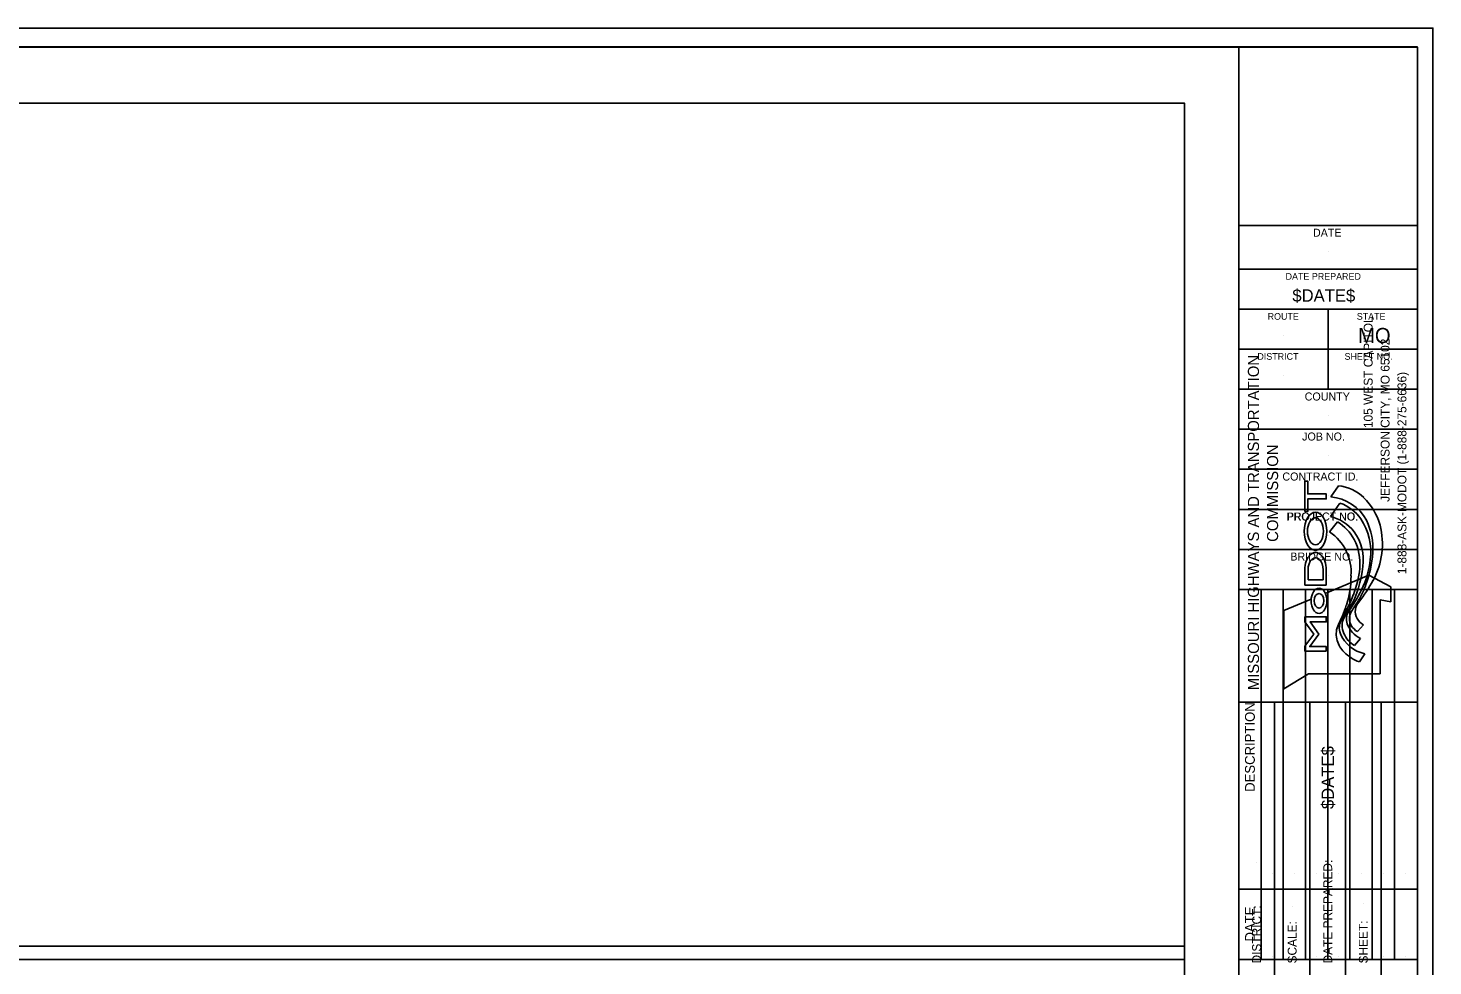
# Model space of a CAD drawing. Extents: x 0 to 31.6, y 0 to 20.8.
# Drawn here: x 15.8 to 31.6, y 10.25 to 20.8 of the extents above; entities that cross this region are included whole.
import ezdxf

# ---------------------------------------------------------------- set-up
doc = ezdxf.new("R2010")
doc.units = 0
for name, color, linetype in [('Border-Border', 7, 'Continuous'), ('Border-Full plan shape', 7, 'Continuous'), ('Border-Full profile shape', 7, 'Continuous'), ('Border-Plan bottom shape', 7, 'Continuous'), ('Border-Plan top shape', 7, 'Continuous'), ('Border-Plotting block', 7, 'Continuous'), ('Border-Title block - Final Plans Consultant Manual Seal', 7, 'Continuous'), ('Border-Title block - Final Plans Electronic Seal', 7, 'Continuous'), ('Border-Title block - Location Survey Electronic Seal', 7, 'Continuous'), ('Border-Xsection shape', 7, 'Continuous')]:
    doc.layers.add(name, color=color, linetype=linetype)

msp = doc.modelspace()

# ---------------------------------------------------------------- linework, layer by layer
at = {"layer": 'Border-Border'}
for p, q in [((0.175, 20.587), (31.425, 20.587)), ((31.425, 20.587), (31.425, 0.212))]:
    msp.add_line(p, q, dxfattribs=at)
at = {"layer": 'Border-Full plan shape'}
msp.add_lwpolyline([(0.806, 19.956), (28.806, 19.956), (28.806, 0.844), (0.806, 0.844)], close=True, dxfattribs=at)
at = {"layer": 'Border-Full profile shape'}
msp.add_lwpolyline([(0.806, 19.956), (28.806, 19.956), (28.806, 0.844), (0.806, 0.844)], close=True, dxfattribs=at)
at = {"layer": 'Border-Plan bottom shape'}
msp.add_lwpolyline([(0.806, 10.325), (28.806, 10.325), (28.806, 0.844), (0.806, 0.844)], close=True, dxfattribs=at)
at = {"layer": 'Border-Plan top shape'}
msp.add_lwpolyline([(0.806, 19.956), (28.806, 19.956), (28.806, 10.475), (0.806, 10.475)], close=True, dxfattribs=at)
at = {"layer": 'Border-Plotting block'}
msp.add_lwpolyline([(0, 0), (31.6, 0), (31.6, 20.8), (0, 20.8)], close=True, dxfattribs=at)
at = {"layer": 'Border-Title block - Final Plans Consultant Manual Seal'}
for p, q in [((29.417, 20.588), (31.425, 20.588)), ((29.417, 20.587), (29.417, 0.212)), ((29.417, 18.58), (31.425, 18.58)), ((30.421, 18.285), (30.421, 18.285)), ((29.417, 18.088), (31.425, 18.088)), ((30.421, 17.793), (30.421, 17.793)), ((29.417, 17.638), (31.425, 17.638)), ((30.421, 16.738), (30.421, 17.638)), ((29.919, 17.343), (29.919, 17.343)), ((30.923, 17.343), (30.923, 17.343)), ((29.417, 17.188), (31.425, 17.188)), ((29.919, 16.895), (29.919, 16.895)), ((30.923, 16.895), (30.923, 16.895)), ((29.417, 16.738), (31.425, 16.738)), ((30.421, 16.443), (30.421, 16.443)), ((29.417, 16.288), (31.425, 16.288)), ((30.421, 15.993), (30.421, 15.993)), ((29.417, 15.838), (31.425, 15.838)), ((30.421, 15.543), (30.421, 15.543)), ((29.417, 15.388), (31.425, 15.388)), ((30.421, 15.093), (30.421, 15.093)), ((29.417, 14.938), (31.425, 14.938)), ((30.421, 14.643), (30.421, 14.643)), ((29.417, 14.488), (31.425, 14.488)), ((29.667, 14.488), (29.667, 10.327)), ((29.917, 14.488), (29.917, 10.327)), ((30.167, 14.488), (30.167, 10.327)), ((30.417, 14.488), (30.417, 10.327)), ((30.667, 14.488), (30.667, 10.327)), ((30.917, 14.488), (30.917, 10.327)), ((31.167, 14.488), (31.167, 10.327)), ((29.417, 11.117), (31.425, 11.117)), ((29.417, 10.327), (31.425, 10.327))]:
    msp.add_line(p, q, dxfattribs=at)
at = {"layer": 'Border-Title block - Final Plans Electronic Seal'}
for p, q in [((29.417, 20.587), (29.417, 0.212)), ((29.417, 18.088), (31.425, 18.088)), ((30.421, 17.793), (30.421, 17.793)), ((29.417, 17.638), (31.425, 17.638)), ((30.421, 16.738), (30.421, 17.638)), ((29.919, 17.343), (29.919, 17.343)), ((30.923, 17.343), (30.923, 17.343)), ((29.417, 17.188), (31.425, 17.188)), ((29.919, 16.895), (29.919, 16.895)), ((30.923, 16.895), (30.923, 16.895)), ((29.417, 16.738), (31.425, 16.738)), ((30.421, 16.443), (30.421, 16.443)), ((29.417, 16.288), (31.425, 16.288)), ((30.421, 15.993), (30.421, 15.993)), ((29.417, 15.838), (31.425, 15.838)), ((30.421, 15.543), (30.421, 15.543)), ((29.417, 15.388), (31.425, 15.388)), ((30.421, 15.093), (30.421, 15.093)), ((29.417, 14.938), (31.425, 14.938)), ((30.421, 14.643), (30.421, 14.643)), ((29.417, 14.488), (31.425, 14.488)), ((29.667, 14.488), (29.667, 10.327)), ((29.917, 14.488), (29.917, 10.327)), ((30.167, 14.488), (30.167, 10.327)), ((30.417, 14.488), (30.417, 10.327)), ((30.667, 14.488), (30.667, 10.327)), ((30.917, 14.488), (30.917, 10.327)), ((31.167, 14.488), (31.167, 10.327)), ((29.792, 11.297), (29.792, 11.297)), ((29.792, 11.297), (29.792, 11.297)), ((30.042, 11.297), (30.042, 11.297)), ((30.042, 11.297), (30.042, 11.297)), ((30.292, 11.297), (30.292, 11.297)), ((30.292, 11.297), (30.292, 11.297)), ((30.542, 11.297), (30.542, 11.297)), ((30.542, 11.297), (30.542, 11.297)), ((30.792, 11.297), (30.792, 11.297)), ((30.792, 11.297), (30.792, 11.297)), ((31.042, 11.297), (31.042, 11.297)), ((31.042, 11.297), (31.042, 11.297)), ((31.296, 11.297), (31.296, 11.297)), ((31.296, 11.297), (31.296, 11.297)), ((29.417, 11.117), (31.425, 11.117)), ((29.417, 10.327), (31.425, 10.327)), ((29.792, 10.362), (29.792, 10.362)), ((29.792, 10.362), (29.792, 10.362)), ((30.042, 10.362), (30.042, 10.362)), ((30.042, 10.362), (30.042, 10.362)), ((30.292, 10.362), (30.292, 10.362)), ((30.292, 10.362), (30.292, 10.362)), ((30.542, 10.362), (30.542, 10.362)), ((30.542, 10.362), (30.542, 10.362)), ((30.792, 10.362), (30.792, 10.362)), ((30.792, 10.362), (30.792, 10.362)), ((31.042, 10.362), (31.042, 10.362)), ((31.042, 10.362), (31.042, 10.362)), ((31.296, 10.362), (31.296, 10.362)), ((31.296, 10.362), (31.296, 10.362))]:
    msp.add_line(p, q, dxfattribs=at)
msp.add_lwpolyline([(29.417, 20.587), (31.425, 20.587), (31.425, 18.088), (29.417, 18.088)], close=True, dxfattribs=at)
at = {"layer": 'Border-Title block - Location Survey Electronic Seal'}
for p, q in [((29.417, 20.587), (29.417, 0.212)), ((29.417, 18.088), (31.425, 18.088)), ((30.537, 15.653), (30.452, 15.528)), ((30.554, 15.458), (30.448, 15.307)), ((30.527, 15.246), (30.438, 15.135)), ((30.16, 14.707), (30.16, 14.534)), ((30.196, 14.594), (30.196, 14.707)), ((30.366, 14.707), (30.366, 14.594)), ((30.401, 14.534), (30.401, 14.707)), ((30.366, 14.594), (30.196, 14.594)), ((30.88, 14.647), (30.39, 14.443)), ((31.127, 14.517), (30.88, 14.647)), ((30.16, 14.534), (30.401, 14.534)), ((31.127, 14.346), (31.127, 14.517)), ((30.231, 14.377), (29.922, 14.249)), ((29.922, 14.249), (29.922, 13.37)), ((31.007, 13.54), (31.007, 14.371)), ((31.007, 14.371), (31.127, 14.346)), ((30.752, 14.013), (30.821, 14.089)), ((30.719, 13.855), (30.786, 13.935)), ((30.773, 13.672), (30.833, 13.764)), ((29.922, 13.37), (30.2, 13.54)), ((30.2, 13.54), (31.007, 13.54)), ((29.417, 13.22), (31.425, 13.22)), ((29.817, 13.22), (29.817, 7.22)), ((30.217, 13.22), (30.217, 7.22)), ((30.617, 13.22), (30.617, 7.22)), ((31.017, 13.22), (31.017, 7.22)), ((29.617, 11.414), (29.617, 11.414)), ((30.017, 10.921), (30.017, 10.921)), ((30.817, 10.95), (30.817, 10.95))]:
    msp.add_line(p, q, dxfattribs=at)
for points in [[(29.417, 20.587), (31.425, 20.587), (31.425, 18.088), (29.417, 18.088)], [(30.16, 15.362), (30.16, 15.706), (30.193, 15.706), (30.193, 15.561), (30.401, 15.561), (30.401, 15.506), (30.193, 15.506), (30.193, 15.362)], [(30.401, 13.794), (30.159, 13.794), (30.159, 13.849), (30.259, 13.985), (30.16, 14.124), (30.16, 14.18), (30.401, 14.18), (30.401, 14.122), (30.219, 14.122), (30.316, 13.985), (30.215, 13.845), (30.401, 13.845)]]:
    msp.add_lwpolyline(points, close=True, dxfattribs=at)
for centre, radius, start, end in [((30.495, 15.189), 0.466, 45.1693, 84.902), ((30.408, 15.023), 0.507, 28.5725, 84.9889), ((30.329, 15.019), 0.703, 15.8221, 45.3322), ((30.395, 14.999), 0.486, 35.4806, 70.8474), ((30.336, 14.844), 0.477, 37.8205, 76.3964), ((30.245, 14.787), 0.539, 29.2666, 58.4191), ((30.246, 14.916), 0.655, 351.9272, 33.854), ((30.192, 14.946), 0.734, 356.2526, 25.8037), ((30.171, 15.001), 0.861, 331.4589, 14.0852), ((30.126, 14.677), 0.554, 55.7274, 55.7276), ((30.126, 14.677), 0.554, 356.1033, 55.7272), ((30.285, 14.82), 0.532, 351.8718, 36.464), ((30.152, 14.776), 0.627, 355.2048, 25.9837), ((29.659, 14.99), 1.269, 339.2778, 355.8465), ((29.624, 14.863), 1.194, 330.8019, 354.3058), ((29.694, 14.828), 1.088, 338.3366, 354.4662), ((29.853, 14.937), 1.048, 334.3097, 353.8237), ((29.663, 14.633), 1.016, 341.469, 0.3416), ((30.017, 14.82), 0.874, 328.3334, 341.428), ((29.009, 15.659), 2.196, 323.2547, 330.8755), ((28.696, 15.2), 2.152, 330.8271, 338.9455), ((28.929, 15.429), 2.094, 325.3377, 333.1413), ((28.593, 15.004), 2.148, 334.3727, 341.1665), ((31.133, 13.94), 0.578, 143.8762, 156.8714), ((30.795, 14.153), 0.167, 149.4043, 197.7638), ((30.814, 14.159), 0.153, 150.2552, 210.6413), ((33.478, 12.556), 3.262, 146.4094, 149.0393), ((30.904, 14.245), 0.177, 174.7527, 241.8661), ((30.912, 14.225), 0.188, 140.188, 168.8506), ((30.749, 13.985), 0.237, 157.7092, 198.1728), ((30.72, 14.057), 0.173, 147.0199, 203.0239), ((30.779, 14.078), 0.2, 153.2735, 205.15), ((30.942, 14.225), 0.33, 202.0629, 241.7201), ((30.852, 14.185), 0.199, 211.4954, 239.6897), ((30.788, 13.982), 0.273, 195.0361, 226.9912), ((30.903, 14.126), 0.368, 201.7288, 258.9961), ((30.858, 14.097), 0.279, 201.8104, 240.1114), ((30.951, 14.138), 0.499, 225.4988, 249.0787)]:
    msp.add_arc(centre, radius, start, end, dxfattribs=at)
for centre, major_axis, ratio in [((30.279, 15.141), (0, 0.214), 0.595517), ((30.279, 15.141), (0, -0.153), 0.589579), ((30.319, 14.36), (0, 0.142), 0.623747), ((30.319, 14.36), (0, 0.0823), 0.65252)]:
    msp.add_ellipse(centre, major_axis=major_axis, ratio=ratio, dxfattribs=at)
for centre, major_axis, ratio in [((30.28, 14.707), (0, -0.196), 0.614143), ((30.281, 14.707), (0, -0.137), 0.62091)]:
    msp.add_ellipse(centre, major_axis=major_axis, ratio=ratio, start_param=1.570796, end_param=4.712389, dxfattribs=at)
at = {"layer": 'Border-Xsection shape'}
msp.add_lwpolyline([(29.417, 0.212), (0.175, 0.212), (0.175, 20.588), (29.417, 20.588)], close=True, dxfattribs=at)

# ---------------------------------------------------------------- texts
at = {"layer": 'Border-Title block - Final Plans Consultant Manual Seal'}
for s, height, p in [('DATE', 0.09, (30.251, 18.454)), ('DATE PREPARED', 0.075, (29.943, 17.97)), ('ROUTE', 0.075, (29.741, 17.52)), ('STATE', 0.075, (30.744, 17.52)), ('MO', 0.17, (30.758, 17.258)), ('DISTRICT', 0.075, (29.626, 17.07)), ('SHEET NO.', 0.075, (30.606, 17.07)), ('COUNTY', 0.09, (30.158, 16.612)), ('JOB NO.', 0.09, (30.129, 16.162)), ('CONTRACT ID.', 0.09, (29.907, 15.712)), ('PROJECT NO.', 0.09, (29.952, 15.262)), ('PROJECT NO.', 0.08858, (29.959, 15.263)), ('BRIDGE NO.', 0.09, (29.996, 14.812))]:
    msp.add_text(s, height=height, dxfattribs=at).set_placement(p)
for s, height, p in [('DESCRIPTION', 0.11024, (29.597, 12.211)), ('DATE', 0.1102, (29.597, 10.528))]:
    msp.add_text(s, height=height, rotation=90, dxfattribs=at).set_placement(p)
at = {"layer": 'Border-Title block - Final Plans Electronic Seal'}
for s, height, p in [('DATE PREPARED', 0.075, (29.943, 17.97)), ('$DATE$', 0.14, (30.019, 17.723)), ('ROUTE', 0.075, (29.741, 17.52)), ('STATE', 0.075, (30.744, 17.52)), ('MO', 0.17, (30.758, 17.258)), ('DISTRICT', 0.075, (29.626, 17.07)), ('SHEET NO.', 0.075, (30.606, 17.07)), ('COUNTY', 0.09, (30.158, 16.612)), ('JOB NO.', 0.09, (30.129, 16.162)), ('CONTRACT ID.', 0.09, (29.907, 15.712)), ('PROJECT NO.', 0.08858, (29.959, 15.263)), ('BRIDGE NO.', 0.09, (29.996, 14.812))]:
    msp.add_text(s, height=height, dxfattribs=at).set_placement(p)
for s, height, p in [('DESCRIPTION', 0.11024, (29.597, 12.211)), ('DATE', 0.1102, (29.597, 10.528))]:
    msp.add_text(s, height=height, rotation=90, dxfattribs=at).set_placement(p)
at = {"layer": 'Border-Title block - Location Survey Electronic Seal'}
for s, height, p in [('105 WEST CAPITOL', 0.1, (30.922, 16.302)), ('JEFFERSON CITY, MO 65102', 0.1, (31.112, 15.472)), ('MISSOURI HIGHWAYS AND TRANSPORTATION', 0.125, (29.644, 13.354)), ('1-888-ASK-MODOT (1-888-275-6636)', 0.1, (31.302, 14.659)), ('COMMISSION', 0.125, (29.859, 15.022)), ('$DATE$', 0.14, (30.487, 12.017)), ('DATE PREPARED:', 0.1, (30.467, 10.281)), ('DISTRICT:', 0.1, (29.667, 10.281)), ('SCALE:', 0.1, (30.067, 10.281)), ('SHEET:', 0.1, (30.867, 10.281))]:
    msp.add_text(s, height=height, rotation=90, dxfattribs=at).set_placement(p)

doc.saveas('drawing.dxf')
